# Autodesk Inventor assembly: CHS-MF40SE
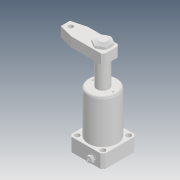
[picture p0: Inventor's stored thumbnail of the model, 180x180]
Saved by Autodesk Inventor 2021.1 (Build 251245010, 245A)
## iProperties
Created: 2019-04
Part Number: CHS-MF40SE
Description: STEP AP203
Document SubType Name: Assembly
Designer: user
Title: chs-mf40s-e_asm.STEP
Revision Number: ÈÎºÎ
Sending System: SolidWorks 2017
Preprocessor: SwSTEP 2.0
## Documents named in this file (9)
- D:\Vault_2016\Projekty\Clamptek\Hydraulic\CHS\CHS-40\Inventor\CHS-MF40SE\CHS-MF40SE.iam
- D:\Vault_2016\Projekty\Clamptek\Hydraulic\CHS\CHS-40\Inventor\CHS-MF40SE\CHS-MF40-11-30-BT.ipt
- D:\Vault_2016\Projekty\Clamptek\Hydraulic\CHS\CHS-40\Inventor\CHS-MF40SE\CHS-40S-02-E.ipt
- D:\Vault_2016\Projekty\Clamptek\Hydraulic\CHS\CHS-40\Inventor\CHS-MF40SE\CHS-40S-01_6.ipt
- D:\Vault_2016\Projekty\Clamptek\Hydraulic\CHS\CHS-40\Inventor\CHS-MF40SE\M18_6.ipt
- D:\Vault_2016\Projekty\Clamptek\Hydraulic\CHS\CHS-40\Inventor\CHS-MF40SE\CHS-TXF-01_2.ipt
- D:\Vault_2016\Projekty\Clamptek\Hydraulic\CHS\CHS-40\Inventor\CHS-MF40SE\CHS-MF40-TXF-03_2.ipt
- D:\Vault_2016\Projekty\Clamptek\Hydraulic\CHS\CHS-40\Inventor\CHS-MF40SE\CHS-MF40-TXF-02_2.ipt
- D:\Vault_2016\Projekty\Clamptek\Hydraulic\CHS\CHS-40\Inventor\CHS-MF40SE\M6_2.ipt
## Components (8 placed, 8 different names)
1. CHS-MF40-11-30-BT_1
2. CHS-40S-02-E_2
3. CHS-40S-01_6_3
4. M18_6_4
5. CHS-TXF-01_2_5
6. CHS-MF40-TXF-03_2_6
7. CHS-MF40-TXF-02_2_7
8. M6_2_8
